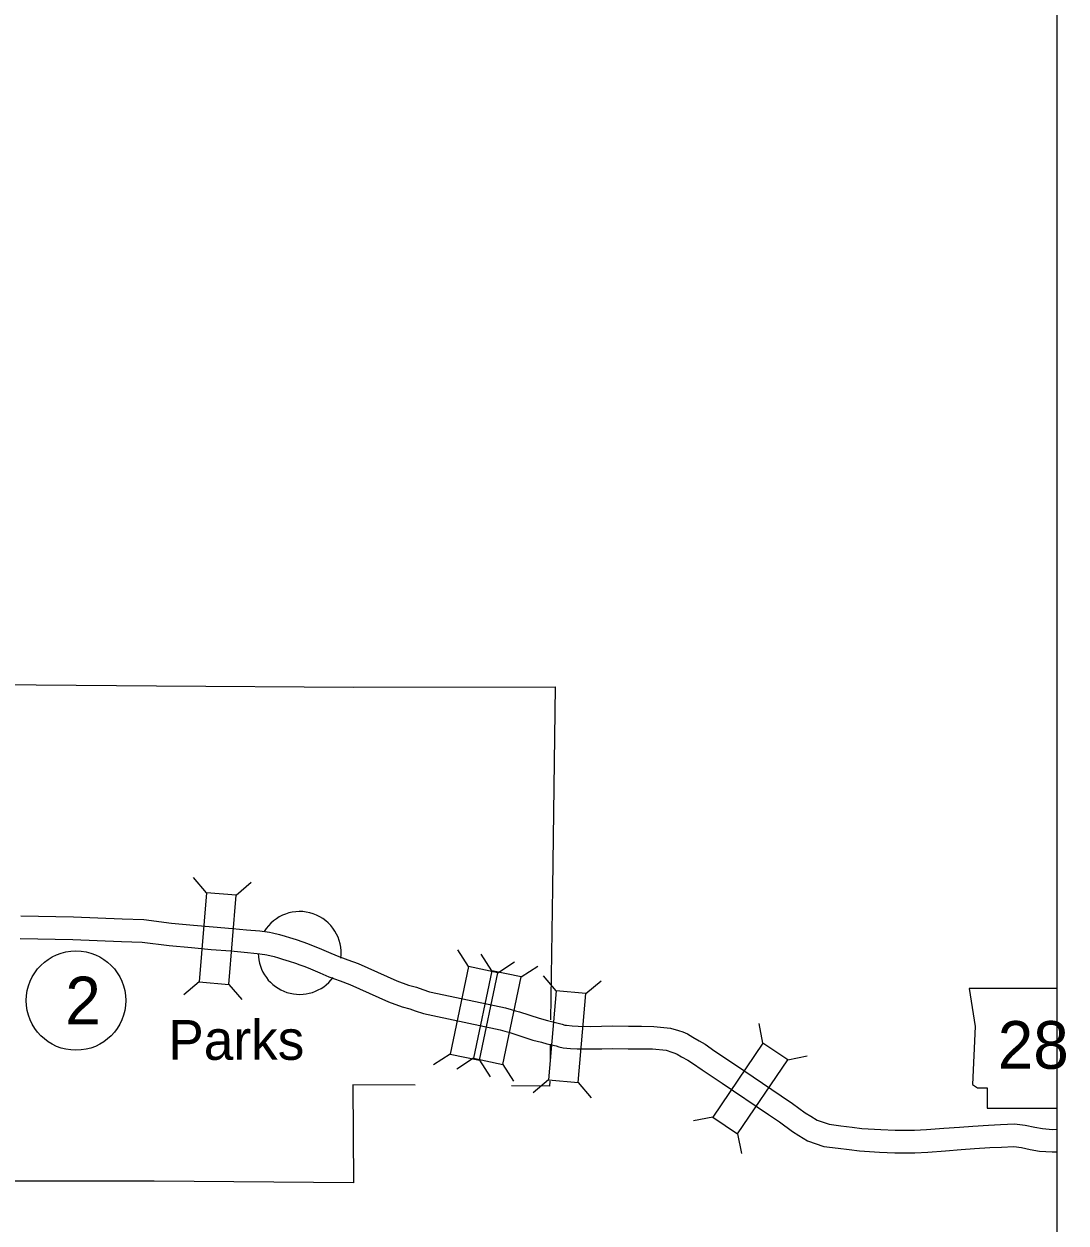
# Model space of a CAD drawing. Extents: x 1382482 to 1385815, y 1168351 to 1170484.
# Drawn here: x 1383234.6 to 1383372.9, y 1169820.9 to 1169980.1 of the extents above; entities that cross this region are included whole.
import ezdxf

# ---------------------------------------------------------------- set-up
doc = ezdxf.new("R2010")
doc.units = 0
for name, color, linetype in [('10', 7, 'Continuous'), ('20', 7, 'Continuous'), ('21', 7, 'Continuous'), ('24', 7, 'Continuous'), ('8', 7, 'Continuous'), ('Default', 7, 'Continuous'), ('R_No Plot', 7, 'Continuous')]:
    doc.layers.add(name, color=color, linetype=linetype)

msp = doc.modelspace()

# ---------------------------------------------------------------- linework, layer by layer
at = {"layer": '10'}
for points in [[(1383234.15, 1169861.66), (1383241.12, 1169861.51), (1383247.61, 1169861.23), (1383250.49, 1169861.15), (1383254.15, 1169860.68), (1383257.05, 1169860.42), (1383259.67, 1169860.19), (1383262.25, 1169859.98), (1383264.08, 1169859.81), (1383265.87, 1169859.65), (1383267.17, 1169859.47), (1383267.53, 1169859.37), (1383268.49, 1169859.16), (1383269.25, 1169858.94), (1383269.8, 1169858.76), (1383270.67, 1169858.49), (1383271.58, 1169858.18), (1383272.21, 1169857.97), (1383272.93, 1169857.68), (1383273.73, 1169857.36), (1383274.98, 1169856.83), (1383276.14, 1169856.34), (1383277.55, 1169855.82), (1383278.94, 1169855.3), (1383284.07, 1169853), (1383285.6, 1169852.46), (1383286.68, 1169852.19), (1383287.49, 1169851.88), (1383288.4, 1169851.57), (1383289.43, 1169851.34), (1383298.49, 1169849.44), (1383299.24, 1169849.22), (1383299.8, 1169849.05), (1383300.35, 1169848.88), (1383302.94, 1169848.05), (1383304.03, 1169847.77), (1383304.74, 1169847.56), (1383306, 1169847.26), (1383306.34, 1169847.15), (1383306.55, 1169847.11), (1383307.32, 1169847.04), (1383308.11, 1169846.99), (1383309.76, 1169846.97), (1383311.19, 1169846.99), (1383312.64, 1169847.04), (1383314.79, 1169847.01), (1383316.51, 1169847.01), (1383318.17, 1169846.96), (1383320.38, 1169846.75), (1383321.44, 1169846.42), (1383321.99, 1169846.24), (1383322.63, 1169845.98), (1383323.35, 1169845.52), (1383324.17, 1169845.07), (1383324.96, 1169844.59), (1383326.25, 1169843.67), (1383328.87, 1169841.94), (1383335.06, 1169837.76), (1383336.57, 1169836.73), (1383338.23, 1169835.51), (1383338.99, 1169835.04), (1383339.84, 1169834.52), (1383341.42, 1169833.97), (1383342.99, 1169833.76), (1383344.47, 1169833.57), (1383345.75, 1169833.41), (1383348.27, 1169833.26), (1383350.19, 1169833.19), (1383352.73, 1169833.2), (1383354.33, 1169833.26), (1383356.65, 1169833.45), (1383358.71, 1169833.6), (1383360.51, 1169833.74), (1383362.58, 1169833.87), (1383364.17, 1169833.94), (1383366.02, 1169834.01), (1383367.45, 1169833.87), (1383368.73, 1169833.57), (1383369.72, 1169833.39), (1383371.08, 1169833.29), (1383371.62, 1169833.31)], [(1383234.07, 1169858.66), (1383241.03, 1169858.51), (1383247.5, 1169858.23), (1383250.26, 1169858.16), (1383253.82, 1169857.7), (1383256.78, 1169857.44), (1383259.41, 1169857.2), (1383262, 1169856.99), (1383263.81, 1169856.82), (1383265.53, 1169856.66), (1383266.55, 1169856.53), (1383266.8, 1169856.45), (1383267.76, 1169856.25), (1383268.36, 1169856.07), (1383268.89, 1169855.9), (1383269.75, 1169855.63), (1383270.6, 1169855.35), (1383271.17, 1169855.15), (1383271.82, 1169854.9), (1383272.58, 1169854.59), (1383273.81, 1169854.07), (1383275.04, 1169853.55), (1383276.51, 1169853.01), (1383277.8, 1169852.53), (1383282.95, 1169850.21), (1383284.74, 1169849.58), (1383285.77, 1169849.32), (1383286.47, 1169849.05), (1383287.59, 1169848.67), (1383288.81, 1169848.41), (1383297.76, 1169846.52), (1383298.38, 1169846.34), (1383298.92, 1169846.18), (1383299.46, 1169846.01), (1383302.1, 1169845.16), (1383303.24, 1169844.87), (1383303.97, 1169844.66), (1383305.18, 1169844.37), (1383305.56, 1169844.25), (1383306.11, 1169844.13), (1383307.09, 1169844.05), (1383308, 1169843.99), (1383309.76, 1169843.97), (1383311.26, 1169843.99), (1383312.68, 1169844.03), (1383314.77, 1169844.01), (1383316.47, 1169844.01), (1383317.98, 1169843.97), (1383319.78, 1169843.8), (1383320.53, 1169843.56), (1383320.96, 1169843.42), (1383321.26, 1169843.3), (1383321.82, 1169842.94), (1383322.67, 1169842.47), (1383323.31, 1169842.08), (1383324.55, 1169841.2), (1383327.21, 1169839.45), (1383333.38, 1169835.28), (1383334.83, 1169834.28), (1383336.55, 1169833.03), (1383337.41, 1169832.48), (1383338.55, 1169831.79), (1383340.71, 1169831.04), (1383342.61, 1169830.78), (1383344.1, 1169830.6), (1383345.47, 1169830.43), (1383348.12, 1169830.26), (1383350.14, 1169830.19), (1383352.79, 1169830.2), (1383354.51, 1169830.27), (1383356.88, 1169830.46), (1383358.93, 1169830.61), (1383360.71, 1169830.74), (1383362.75, 1169830.87), (1383364.3, 1169830.95), (1383365.92, 1169831.01), (1383366.96, 1169830.9), (1383368.12, 1169830.63), (1383369.34, 1169830.41), (1383371.02, 1169830.29), (1383371.62, 1169830.31)]]:
    msp.add_lwpolyline(points, dxfattribs=at)
at = {"layer": '20'}
for p, q in [((1383258.78, 1169864.71), (1383257.07, 1169866.72)), ((1383262.72, 1169864.39), (1383264.74, 1169866.1)), ((1383293.57, 1169854.91), (1383292.13, 1169857.12)), ((1383296.67, 1169854.36), (1383295.23, 1169856.57)), ((1383297.45, 1169854.1), (1383299.66, 1169855.54)), ((1383300.54, 1169853.54), (1383302.75, 1169854.98)), ((1383305.21, 1169851.68), (1383303.51, 1169853.7)), ((1383257.81, 1169852.87), (1383255.8, 1169851.16)), ((1383261.76, 1169852.55), (1383263.47, 1169850.54)), ((1383309.15, 1169851.34), (1383311.17, 1169853.03)), ((1383332.64, 1169844.75), (1383332.14, 1169847.35)), ((1383291.13, 1169843.29), (1383288.92, 1169841.85)), ((1383294.22, 1169842.73), (1383292.01, 1169841.29)), ((1383295, 1169842.47), (1383296.44, 1169840.26)), ((1383335.92, 1169842.54), (1383338.52, 1169843.04)), ((1383298.1, 1169841.92), (1383299.54, 1169839.7)), ((1383304.17, 1169839.85), (1383302.15, 1169838.15)), ((1383308.12, 1169839.5), (1383309.82, 1169837.48)), ((1383325.99, 1169834.91), (1383323.4, 1169834.41)), ((1383329.27, 1169832.69), (1383329.77, 1169830.1))]:
    msp.add_line(p, q, dxfattribs=at)
for points in [[(1383258.78, 1169864.71), (1383257.81, 1169852.87), (1383261.76, 1169852.55), (1383262.72, 1169864.39)], [(1383293.57, 1169854.91), (1383291.13, 1169843.29), (1383295, 1169842.47), (1383297.45, 1169854.1)], [(1383296.67, 1169854.36), (1383294.22, 1169842.73), (1383298.1, 1169841.92), (1383300.54, 1169853.54)], [(1383305.21, 1169851.68), (1383304.17, 1169839.85), (1383308.12, 1169839.5), (1383309.15, 1169851.34)], [(1383332.64, 1169844.75), (1383325.99, 1169834.91), (1383329.27, 1169832.69), (1383335.92, 1169842.54)]]:
    msp.add_lwpolyline(points, close=True, dxfattribs=at)
at = {"layer": '21'}
msp.add_lwpolyline([(1383371.62, 1169852.01), (1383360.02, 1169852.01), (1383360.78, 1169846.94), (1383360.44, 1169839.24), (1383361.12, 1169838.82), (1383362.39, 1169838.82), (1383362.39, 1169836.11), (1383371.62, 1169836.11)], dxfattribs=at)
at = {"layer": '24'}
for start, end in [(352.9988, 148.8271), (180.6647, 323.5087)]:
    msp.add_arc((1383271.16, 1169856.72), 5.5, start, end, dxfattribs=at)
at = {"layer": '8'}
for points in [[(1383211.99, 1169892.52), (1383225.47, 1169892.43), (1383252.17, 1169892.21), (1383278.32, 1169892.03), (1383305.05, 1169892.06), (1383304.71, 1169865.38), (1383304.46, 1169847.84)], [(1383304.41, 1169844.62), (1383304.38, 1169842.31)], [(1383286.47, 1169839.16), (1383278.2, 1169839.22), (1383278.3, 1169826.18), (1383251.85, 1169826.43), (1383225.48, 1169826.43), (1383212.51, 1169826.58)], [(1383304.34, 1169839.69), (1383304.33, 1169839.02), (1383299.25, 1169839.06)]]:
    msp.add_lwpolyline(points, dxfattribs=at)
at = {"layer": 'Default'}
msp.add_circle((1383241.47, 1169850.4), 6.6, dxfattribs=at)
at = {"layer": 'R_No Plot'}
msp.add_lwpolyline([(1382642.23, 1170388.77), (1383371.62, 1170388.77), (1383371.62, 1169604.28), (1382642.23, 1169604.28)], close=True, dxfattribs=at)

# ---------------------------------------------------------------- texts
at = {"layer": '21'}
msp.add_text('28', height=6.336, dxfattribs=at).set_placement((1383363.8, 1169841.34))
at = {"layer": '24'}
msp.add_text('Parks', height=5.28, dxfattribs=at).set_placement((1383253.72, 1169842.53))
at = {"layer": 'Default'}
msp.add_text('2', height=6.34, dxfattribs=at).set_placement((1383240.05, 1169847.23))

doc.saveas('drawing.dxf')
